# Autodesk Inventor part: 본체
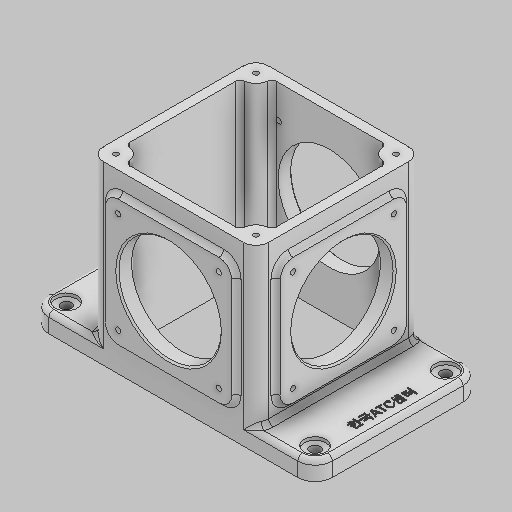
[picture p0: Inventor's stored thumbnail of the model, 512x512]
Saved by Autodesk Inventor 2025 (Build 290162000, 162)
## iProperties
Created: 2024-08
Part Number: 본체
Material: 일반
Document SubType Name: Modeling
Designer: 현기
Density: 1 g/cm^3
Appearance: 기본값
Author: jhkim
Sending System: Autodesk Inventor 2025
Preprocessor: ST-DEVELOPER v20
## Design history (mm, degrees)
feature "솔리드1"
node "솔리드2"
